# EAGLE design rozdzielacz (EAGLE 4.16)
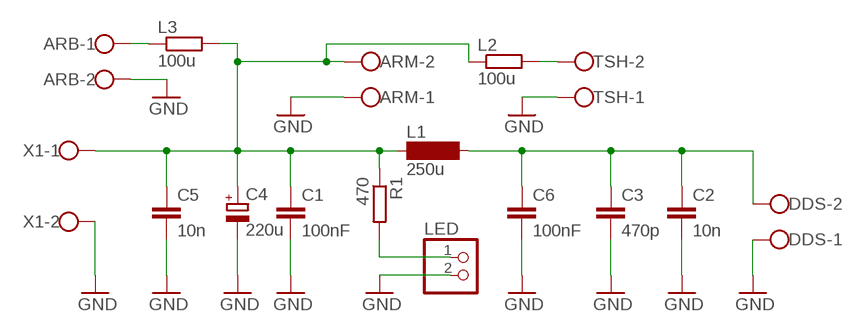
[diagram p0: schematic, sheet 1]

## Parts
ARB  W237-102  [W237-102]
ARM  W237-102  [W237-102]
C1  100nF  C-EUC1206K  [C1206K]
C2  10n  C-EUC0805K  [C0805K]
C3  470p  C-EUC0603K  [C0603K]
C4  220u  CPOL-EUE3.5-8  [E3,5-8]
C5  10n  C-EUC0805K  [C0805K]
C6  100nF  C-EUC1206K  [C1206K]
DDS  W237-102  [W237-102]
L1  250u  MS85  [MS85]
L2  100u  R-EU_0204/5  [0204/5]
L3  100u  R-EU_0204/5  [0204/5]
LED  PINHD-1X2  [1X02]
R1  470  R-EU_R0603  [R0603]
TSH  W237-102  [W237-102]
X1  W237-102  [W237-102]

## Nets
GND: ARB.2 ARM.1 C1.2 C2.2 C3.2 C4.- C5.2 C6.2 DDS.1 LED.2 TSH.1 X1.2
N$1: ARM.2 C1.1 C4.+ C5.1 L1.1 L2.1 L3.2 R1.1 X1.1
N$2: C2.1 C3.1 C6.1 DDS.2 L1.2
N$3: LED.1 R1.2
N$4: L2.2 TSH.2
N$5: ARB.1 L3.1

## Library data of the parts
ARB ARM DDS TSH X1 = con-wago-500:W237-102: WAGO SCREW CLAMP
C1-C3 C5 C6 = rcl:C-EU: CAPACITOR, European symbol
C4 = rcl:CPOL-EU: POLARIZED CAPACITOR, European symbol
L1 = inductor-neosid:MS85: INDUCTOR
L2 L3 R1 = rcl:R-EU_: RESISTOR, European symbol
LED = pinhead:PINHD-1X2: PIN HEADER

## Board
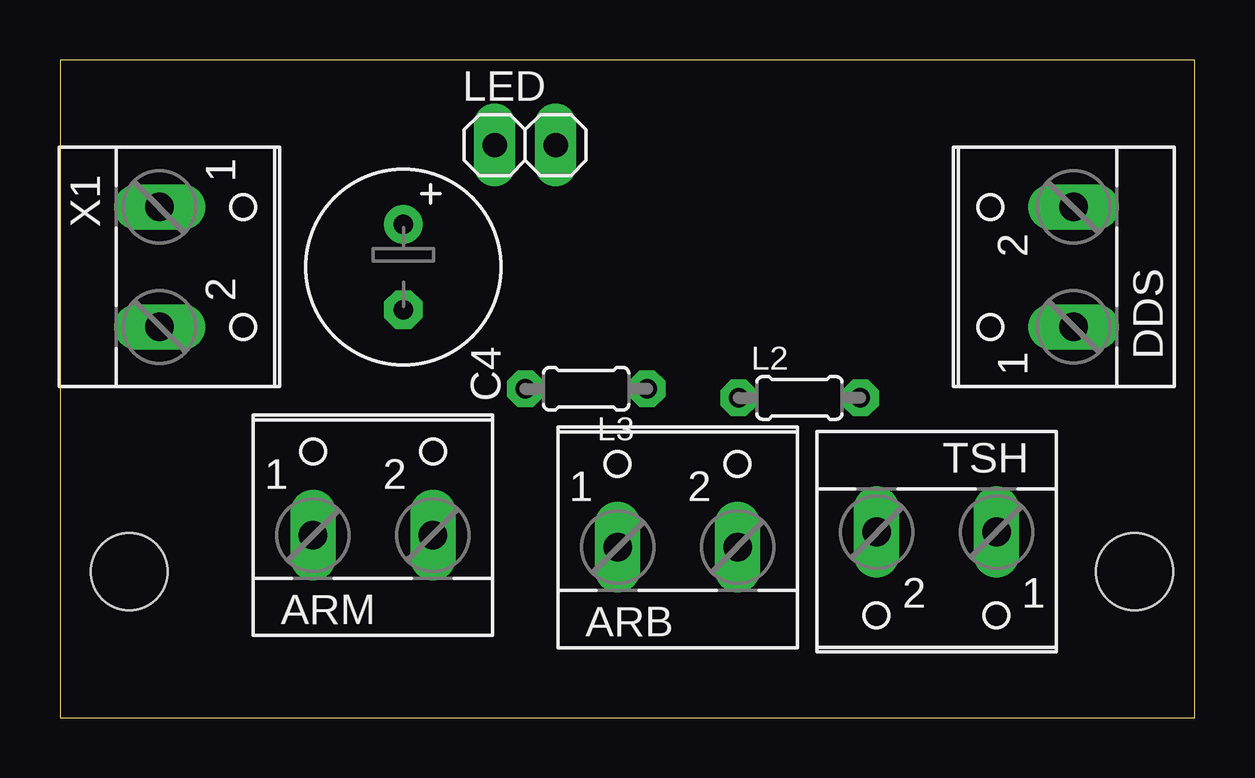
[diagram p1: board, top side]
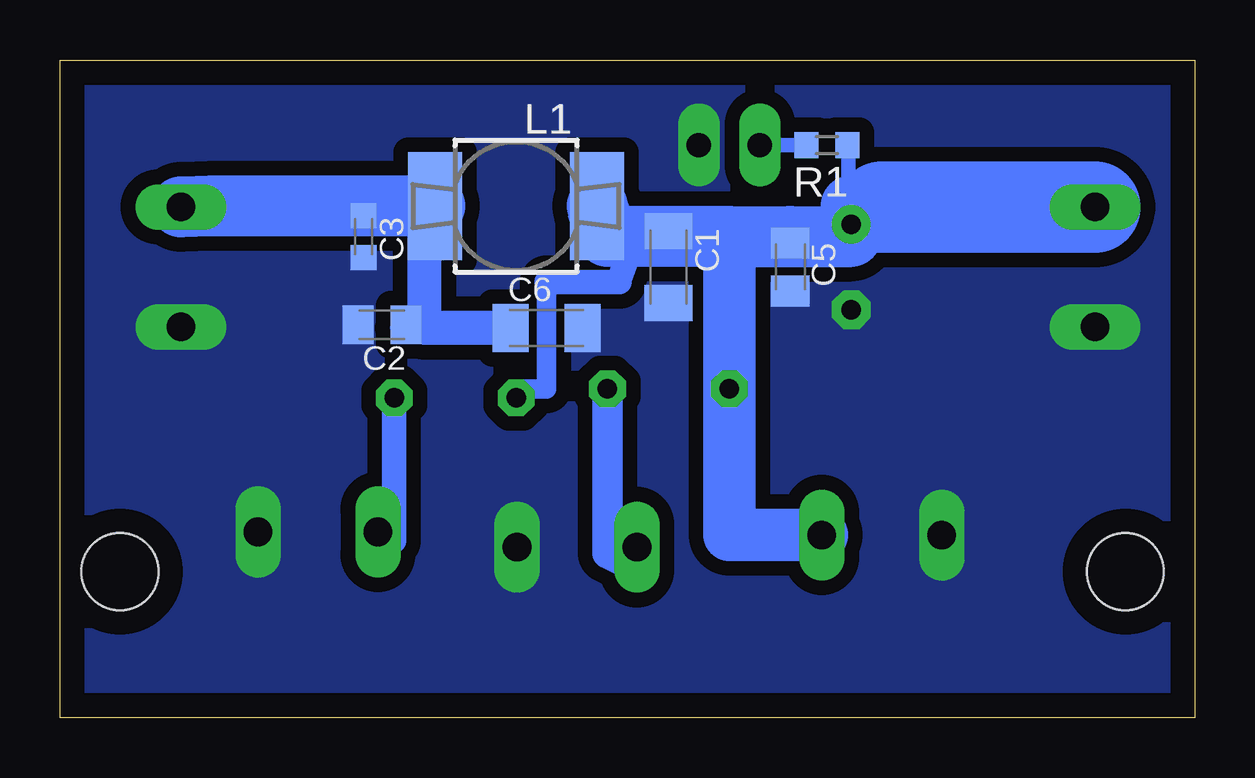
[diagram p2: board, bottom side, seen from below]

Size 47.3 x 27.42 mm. Coordinates in mm from the lower left corner, seen from the top.
Outline: 0,0 47.3,0 47.3,27.42 0,27.42 0,0
Copper layers (1*16): Top 0.035mm / dielectric 1.5mm / Bottom 0.035mm
Design rules "default": minimum track width 15mil, minimum drill 24mil, track to track 8mil, track to pad 8mil, pad to pad 8mil, via to via 8mil, smd to smd 8mil, copper to edge 40mil, drill to drill 8mil, minimum pad ring 14mil, minimum via ring 8mil, stop-mask expansion 4mil, vias tented up to drill 0mil, thermal gap 10mil
Holes 3.2 mm at 2.88,6.09 44.79,6.09

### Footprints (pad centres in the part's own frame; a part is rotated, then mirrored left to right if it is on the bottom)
W237-102 = drill 1.194 long: 1 -2.5,-1.27; 2 2.5,-1.27
C1206K = smd 1.5 x 2: 1 -1.5,0; 2 1.5,0
C0805K = smd 1.3 x 1.6: 1 -1,0; 2 1,0
C0603K = smd 1.05 x 1.08: 1 -0.875,0; 2 0.875,0
E3,5-8 = drill 0.813 pad 1.6 round: + -1.778,0 | drill 0.813 pad 1.6 octagon: - 1.778,0
MS85 = smd 4.5 x 2.25: 1 0,-3.383; 2 0,3.383
0204/5 = drill 0.813 octagon: 1 -2.54,0; 2 2.54,0
1X02 = drill 1.016 long: 1 -1.27,0; 2 1.27,0
R0603 = smd 1 x 1.1: 1 -0.85,0; 2 0.85,0

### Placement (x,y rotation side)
ARB  25.74,8.38 0 top
ARM  13.04,8.88 0 top
C1  21.93,18.79 270 bottom
C2  33.87,16.38 180 bottom
C3  34.63,20.06 270 bottom
C4  14.31,18.79 270 top
C5  16.85,18.79 270 bottom
C6  27.01,16.25 0 bottom
DDS  40.98,18.79 90 top
L1  28.28,21.33 90 bottom
L2  30.82,13.33 0 top
L3  21.93,13.71 180 top
LED  19.39,23.87 0 top
R1  15.33,23.87 180 bottom
TSH  36.54,6.47 180 top
X1  5.42,18.79 270 top

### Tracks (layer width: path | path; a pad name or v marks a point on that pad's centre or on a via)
GND
  pour Bottom (isolate 0.61, no thermals): 0.09,27.68 0.09,-0.39 46.95,-0.39 46.95,27.68
N$1
  Bottom 0.381: 16.85,20.06 C5.1 | 20.66,20.06 C1.1 | 28.28,13.71 L2.1
  Bottom 0.406: 13.04,21.33 13.04,21.29 | 14.31,21.33 14.44,21.33 | 14.44,23.87 R1.1
  Bottom 0.61: 14.44,21.33 14.44,23.87 | 23.96,18.28 23.96,18.16
  Bottom 0.813: 28.28,13.71 27.01,13.71 27.01,18.16
  Bottom 1.016: 23.96,18.16 27.01,18.16 | 23.33,20.06 23.96,18.28
  Bottom 2.184: 19.39,20.06 L3.2 19.39,7.62 ARM.2
  Bottom 2.54: L1.1 24.47,20.06 23.33,20.06 20.66,20.06 19.39,20.06 16.85,20.06 14.31,20.06 C4.+ 14.31,21.33 13.04,21.33
  Bottom 3.81: 13.04,21.29 X1.1
N$2
  Bottom 0.381: 34.63,21.33 C3.1 | 32.09,16.25 33.36,16.25 C2.1 | 32.09,20.06 L1.2
  Bottom 0.813: C6.1 28.28,16.25
  Bottom 1.422: C6.1 32.09,16.25 32.09,20.06
  Bottom 2.54: L1.2 34.63,21.33 40.98,21.33 DDS.2
N$3
  Bottom 0.61: R1.2 LED.1
N$4
  Bottom 0.381: L2.2 33.36,13.71
  Bottom 1.016: L2.2 33.36,7.36 TSH.2
N$5
  Bottom 1.27: L3.1 24.47,6.85 22.95,6.09 ARB.1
